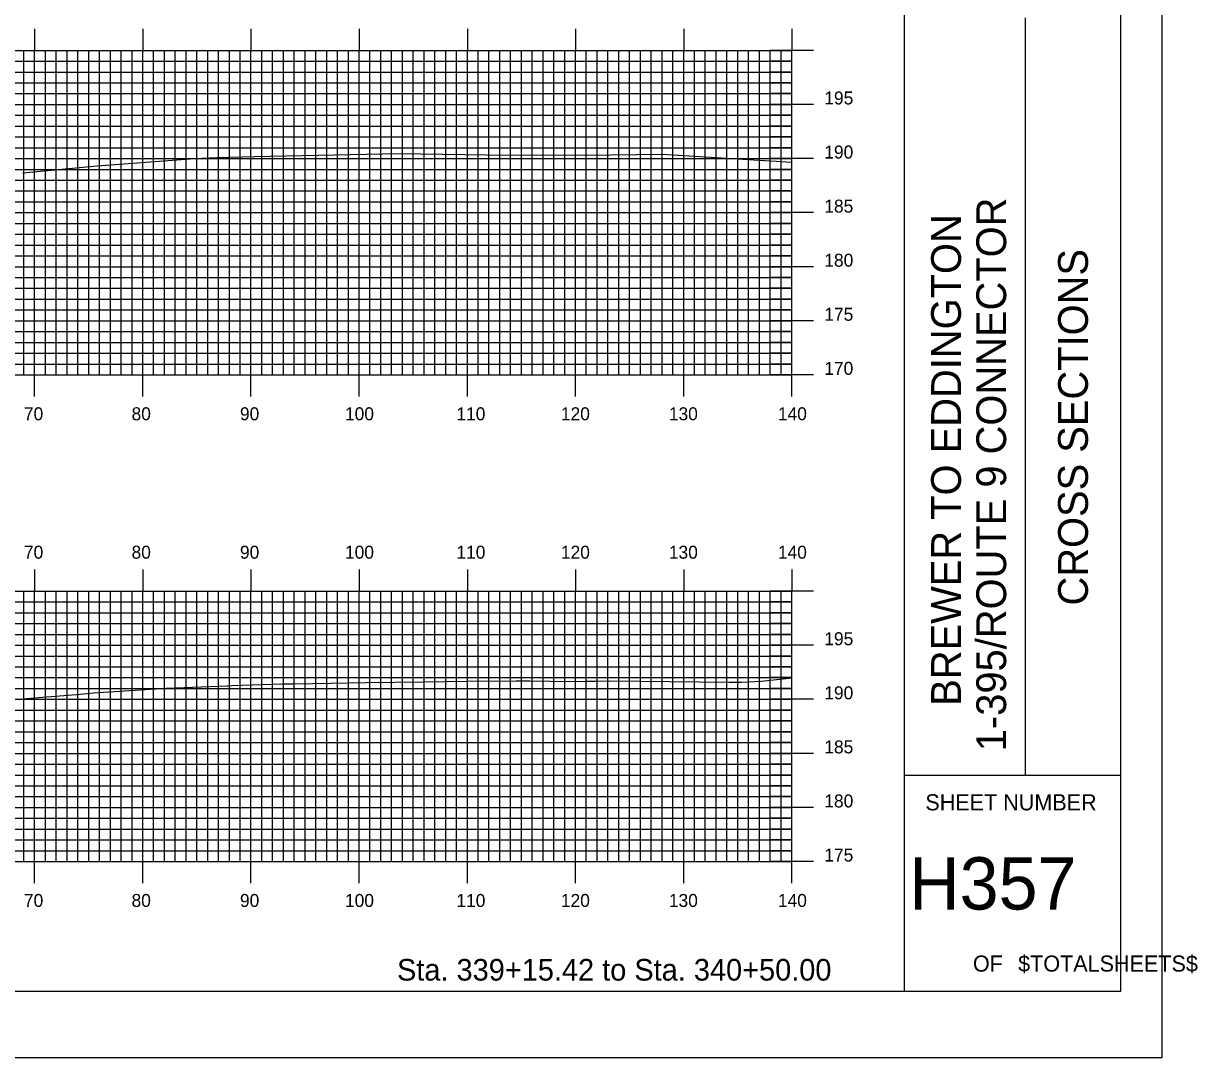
# Model space of a CAD drawing. Extents: x 1824360 to 1824703, y 442591 to 442811.
# Drawn here: x 1824594.3 to 1824702.8, y 442590.5 to 442686.2 of the extents above; entities that cross this region are included whole.
import ezdxf

# ---------------------------------------------------------------- set-up
doc = ezdxf.new("R2010")
doc.units = 0
for name, color, linetype in [('BORDER', 7, 'Continuous'), ('H_V ANNOTATION', 7, 'Continuous'), ('MAJOR', 7, 'Continuous'), ('MINOR', 7, 'Continuous'), ('PLOT BOUNDARY', 7, 'Continuous'), ('S_Roadway_Centerline', 7, 'Continuous')]:
    doc.layers.add(name, color=color, linetype=linetype)

msp = doc.modelspace()

# ---------------------------------------------------------------- linework, layer by layer
at = {"layer": 'BORDER'}
for p, q in [((1824675.73, 442596.67), (1824675.73, 442806.67)), ((1824686.92, 442616.67), (1824686.92, 442686.67)), ((1824675.73, 442616.67), (1824695.73, 442616.67))]:
    msp.add_line(p, q, dxfattribs=at)
msp.add_lwpolyline([(1824375.73, 442596.67), (1824695.73, 442596.67), (1824695.73, 442806.67), (1824375.73, 442806.67)], close=True, dxfattribs=at)
at = {"layer": 'MAJOR'}
for p, q in [((1824595.33, 442685.67), (1824595.33, 442683.67)), ((1824605.33, 442685.67), (1824605.33, 442683.67)), ((1824615.33, 442685.67), (1824615.33, 442683.67)), ((1824625.33, 442685.67), (1824625.33, 442683.67)), ((1824635.33, 442685.67), (1824635.33, 442683.67)), ((1824645.33, 442685.67), (1824645.33, 442683.67)), ((1824655.33, 442685.67), (1824655.33, 442683.67)), ((1824665.33, 442685.67), (1824665.33, 442683.67)), ((1824385.33, 442683.67), (1824665.33, 442683.67)), ((1824385.33, 442683.67), (1824665.33, 442683.67)), ((1824595.33, 442653.67), (1824595.33, 442683.67)), ((1824605.33, 442653.67), (1824605.33, 442683.67)), ((1824615.33, 442653.67), (1824615.33, 442683.67)), ((1824625.33, 442653.67), (1824625.33, 442683.67)), ((1824635.33, 442653.67), (1824635.33, 442683.67)), ((1824645.33, 442653.67), (1824645.33, 442683.67)), ((1824655.33, 442653.67), (1824655.33, 442683.67)), ((1824667.34, 442683.67), (1824663.33, 442683.67)), ((1824665.33, 442653.67), (1824665.33, 442683.67)), ((1824665.33, 442653.67), (1824665.33, 442683.67)), ((1824385.33, 442678.67), (1824665.33, 442678.67)), ((1824667.34, 442678.67), (1824663.33, 442678.67)), ((1824385.33, 442673.67), (1824665.33, 442673.67)), ((1824667.34, 442673.67), (1824663.33, 442673.67)), ((1824385.33, 442668.67), (1824665.33, 442668.67)), ((1824667.34, 442668.67), (1824663.33, 442668.67)), ((1824385.33, 442663.67), (1824665.33, 442663.67)), ((1824667.34, 442663.67), (1824663.33, 442663.67)), ((1824385.33, 442658.67), (1824665.33, 442658.67)), ((1824667.34, 442658.67), (1824663.33, 442658.67)), ((1824385.33, 442653.67), (1824665.33, 442653.67)), ((1824385.33, 442653.67), (1824665.33, 442653.67)), ((1824595.33, 442651.66), (1824595.33, 442653.67)), ((1824605.33, 442651.66), (1824605.33, 442653.67)), ((1824615.33, 442651.66), (1824615.33, 442653.67)), ((1824625.33, 442651.66), (1824625.33, 442653.67)), ((1824635.33, 442651.66), (1824635.33, 442653.67)), ((1824645.33, 442651.66), (1824645.33, 442653.67)), ((1824655.33, 442651.66), (1824655.33, 442653.67)), ((1824667.34, 442653.67), (1824663.33, 442653.67)), ((1824665.33, 442651.66), (1824665.33, 442653.67)), ((1824595.33, 442635.67), (1824595.33, 442633.67)), ((1824605.33, 442635.67), (1824605.33, 442633.67)), ((1824615.33, 442635.67), (1824615.33, 442633.67)), ((1824625.33, 442635.67), (1824625.33, 442633.67)), ((1824635.33, 442635.67), (1824635.33, 442633.67)), ((1824645.33, 442635.67), (1824645.33, 442633.67)), ((1824655.33, 442635.67), (1824655.33, 442633.67)), ((1824665.33, 442635.67), (1824665.33, 442633.67)), ((1824525.33, 442633.67), (1824665.33, 442633.67)), ((1824525.33, 442633.67), (1824665.33, 442633.67)), ((1824595.33, 442608.67), (1824595.33, 442633.67)), ((1824605.33, 442608.67), (1824605.33, 442633.67)), ((1824615.33, 442608.67), (1824615.33, 442633.67)), ((1824625.33, 442608.67), (1824625.33, 442633.67)), ((1824635.33, 442608.67), (1824635.33, 442633.67)), ((1824645.33, 442608.67), (1824645.33, 442633.67)), ((1824655.33, 442608.67), (1824655.33, 442633.67)), ((1824667.34, 442633.67), (1824663.33, 442633.67)), ((1824665.33, 442608.67), (1824665.33, 442633.67)), ((1824665.33, 442608.67), (1824665.33, 442633.67)), ((1824525.33, 442628.67), (1824665.33, 442628.67)), ((1824667.34, 442628.67), (1824663.33, 442628.67)), ((1824525.33, 442623.67), (1824665.33, 442623.67)), ((1824667.34, 442623.67), (1824663.33, 442623.67)), ((1824525.33, 442618.67), (1824665.33, 442618.67)), ((1824667.34, 442618.67), (1824663.33, 442618.67)), ((1824525.33, 442613.67), (1824665.33, 442613.67)), ((1824667.34, 442613.67), (1824663.33, 442613.67)), ((1824525.33, 442608.67), (1824665.33, 442608.67)), ((1824525.33, 442608.67), (1824665.33, 442608.67)), ((1824595.33, 442606.66), (1824595.33, 442608.67)), ((1824605.33, 442606.66), (1824605.33, 442608.67)), ((1824615.33, 442606.66), (1824615.33, 442608.67)), ((1824625.33, 442606.66), (1824625.33, 442608.67)), ((1824635.33, 442606.66), (1824635.33, 442608.67)), ((1824645.33, 442606.66), (1824645.33, 442608.67)), ((1824655.33, 442606.66), (1824655.33, 442608.67)), ((1824667.34, 442608.67), (1824663.33, 442608.67)), ((1824665.33, 442606.66), (1824665.33, 442608.67))]:
    msp.add_line(p, q, dxfattribs=at)
at = {"layer": 'MINOR'}
for p, q in [((1824594.33, 442653.67), (1824594.33, 442683.67)), ((1824596.33, 442653.67), (1824596.33, 442683.67)), ((1824597.33, 442653.67), (1824597.33, 442683.67)), ((1824598.33, 442653.67), (1824598.33, 442683.67)), ((1824599.33, 442653.67), (1824599.33, 442683.67)), ((1824600.33, 442653.67), (1824600.33, 442683.67)), ((1824601.33, 442653.67), (1824601.33, 442683.67)), ((1824602.33, 442653.67), (1824602.33, 442683.67)), ((1824603.33, 442653.67), (1824603.33, 442683.67)), ((1824604.33, 442653.67), (1824604.33, 442683.67)), ((1824606.33, 442653.67), (1824606.33, 442683.67)), ((1824607.33, 442653.67), (1824607.33, 442683.67)), ((1824608.33, 442653.67), (1824608.33, 442683.67)), ((1824609.33, 442653.67), (1824609.33, 442683.67)), ((1824610.33, 442653.67), (1824610.33, 442683.67)), ((1824611.33, 442653.67), (1824611.33, 442683.67)), ((1824612.33, 442653.67), (1824612.33, 442683.67)), ((1824613.33, 442653.67), (1824613.33, 442683.67)), ((1824614.33, 442653.67), (1824614.33, 442683.67)), ((1824616.33, 442653.67), (1824616.33, 442683.67)), ((1824617.33, 442653.67), (1824617.33, 442683.67)), ((1824618.33, 442653.67), (1824618.33, 442683.67)), ((1824619.33, 442653.67), (1824619.33, 442683.67)), ((1824620.33, 442653.67), (1824620.33, 442683.67)), ((1824621.33, 442653.67), (1824621.33, 442683.67)), ((1824622.33, 442653.67), (1824622.33, 442683.67)), ((1824623.33, 442653.67), (1824623.33, 442683.67)), ((1824624.33, 442653.67), (1824624.33, 442683.67)), ((1824626.33, 442653.67), (1824626.33, 442683.67)), ((1824627.33, 442653.67), (1824627.33, 442683.67)), ((1824628.33, 442653.67), (1824628.33, 442683.67)), ((1824629.33, 442653.67), (1824629.33, 442683.67)), ((1824630.33, 442653.67), (1824630.33, 442683.67)), ((1824631.33, 442653.67), (1824631.33, 442683.67)), ((1824632.33, 442653.67), (1824632.33, 442683.67)), ((1824633.33, 442653.67), (1824633.33, 442683.67)), ((1824634.33, 442653.67), (1824634.33, 442683.67)), ((1824636.33, 442653.67), (1824636.33, 442683.67)), ((1824637.33, 442653.67), (1824637.33, 442683.67)), ((1824638.33, 442653.67), (1824638.33, 442683.67)), ((1824639.33, 442653.67), (1824639.33, 442683.67)), ((1824640.33, 442653.67), (1824640.33, 442683.67)), ((1824641.33, 442653.67), (1824641.33, 442683.67)), ((1824642.33, 442653.67), (1824642.33, 442683.67)), ((1824643.33, 442653.67), (1824643.33, 442683.67)), ((1824644.33, 442653.67), (1824644.33, 442683.67)), ((1824646.33, 442653.67), (1824646.33, 442683.67)), ((1824647.33, 442653.67), (1824647.33, 442683.67)), ((1824648.33, 442653.67), (1824648.33, 442683.67)), ((1824649.33, 442653.67), (1824649.33, 442683.67)), ((1824650.33, 442653.67), (1824650.33, 442683.67)), ((1824651.33, 442653.67), (1824651.33, 442683.67)), ((1824652.33, 442653.67), (1824652.33, 442683.67)), ((1824653.33, 442653.67), (1824653.33, 442683.67)), ((1824654.33, 442653.67), (1824654.33, 442683.67)), ((1824656.33, 442653.67), (1824656.33, 442683.67)), ((1824657.33, 442653.67), (1824657.33, 442683.67)), ((1824658.33, 442653.67), (1824658.33, 442683.67)), ((1824659.33, 442653.67), (1824659.33, 442683.67)), ((1824660.33, 442653.67), (1824660.33, 442683.67)), ((1824661.33, 442653.67), (1824661.33, 442683.67)), ((1824662.33, 442653.67), (1824662.33, 442683.67)), ((1824663.33, 442653.67), (1824663.33, 442683.67)), ((1824664.33, 442653.67), (1824664.33, 442683.67)), ((1824385.33, 442682.67), (1824665.33, 442682.67)), ((1824665.33, 442682.67), (1824663.33, 442682.67)), ((1824385.33, 442681.67), (1824665.33, 442681.67)), ((1824665.33, 442681.67), (1824663.33, 442681.67)), ((1824385.33, 442680.67), (1824665.33, 442680.67)), ((1824665.33, 442680.67), (1824663.33, 442680.67)), ((1824385.33, 442679.67), (1824665.33, 442679.67)), ((1824665.33, 442679.67), (1824663.33, 442679.67)), ((1824385.33, 442677.67), (1824665.33, 442677.67)), ((1824665.33, 442677.67), (1824663.33, 442677.67)), ((1824385.33, 442676.67), (1824665.33, 442676.67)), ((1824665.33, 442676.67), (1824663.33, 442676.67)), ((1824385.33, 442675.67), (1824665.33, 442675.67)), ((1824665.33, 442675.67), (1824663.33, 442675.67)), ((1824385.33, 442674.67), (1824665.33, 442674.67)), ((1824665.33, 442674.67), (1824663.33, 442674.67)), ((1824385.33, 442672.67), (1824665.33, 442672.67)), ((1824385.33, 442671.67), (1824665.33, 442671.67)), ((1824665.33, 442672.67), (1824663.33, 442672.67)), ((1824665.33, 442671.67), (1824663.33, 442671.67)), ((1824385.33, 442670.67), (1824665.33, 442670.67)), ((1824665.33, 442670.67), (1824663.33, 442670.67)), ((1824385.33, 442669.67), (1824665.33, 442669.67)), ((1824665.33, 442669.67), (1824663.33, 442669.67)), ((1824385.33, 442667.67), (1824665.33, 442667.67)), ((1824665.33, 442667.67), (1824663.33, 442667.67)), ((1824385.33, 442666.67), (1824665.33, 442666.67)), ((1824665.33, 442666.67), (1824663.33, 442666.67)), ((1824385.33, 442665.67), (1824665.33, 442665.67)), ((1824665.33, 442665.67), (1824663.33, 442665.67)), ((1824385.33, 442664.67), (1824665.33, 442664.67)), ((1824665.33, 442664.67), (1824663.33, 442664.67)), ((1824385.33, 442662.67), (1824665.33, 442662.67)), ((1824665.33, 442662.67), (1824663.33, 442662.67)), ((1824385.33, 442661.67), (1824665.33, 442661.67)), ((1824665.33, 442661.67), (1824663.33, 442661.67)), ((1824385.33, 442660.67), (1824665.33, 442660.67)), ((1824385.33, 442659.67), (1824665.33, 442659.67)), ((1824665.33, 442660.67), (1824663.33, 442660.67)), ((1824665.33, 442659.67), (1824663.33, 442659.67)), ((1824385.33, 442657.67), (1824665.33, 442657.67)), ((1824665.33, 442657.67), (1824663.33, 442657.67)), ((1824385.33, 442656.67), (1824665.33, 442656.67)), ((1824665.33, 442656.67), (1824663.33, 442656.67)), ((1824385.33, 442655.67), (1824665.33, 442655.67)), ((1824665.33, 442655.67), (1824663.33, 442655.67)), ((1824385.33, 442654.67), (1824665.33, 442654.67)), ((1824665.33, 442654.67), (1824663.33, 442654.67)), ((1824594.33, 442608.67), (1824594.33, 442633.67)), ((1824596.33, 442608.67), (1824596.33, 442633.67)), ((1824597.33, 442608.67), (1824597.33, 442633.67)), ((1824598.33, 442608.67), (1824598.33, 442633.67)), ((1824599.33, 442608.67), (1824599.33, 442633.67)), ((1824600.33, 442608.67), (1824600.33, 442633.67)), ((1824601.33, 442608.67), (1824601.33, 442633.67)), ((1824602.33, 442608.67), (1824602.33, 442633.67)), ((1824603.33, 442608.67), (1824603.33, 442633.67)), ((1824604.33, 442608.67), (1824604.33, 442633.67)), ((1824606.33, 442608.67), (1824606.33, 442633.67)), ((1824607.33, 442608.67), (1824607.33, 442633.67)), ((1824608.33, 442608.67), (1824608.33, 442633.67)), ((1824609.33, 442608.67), (1824609.33, 442633.67)), ((1824610.33, 442608.67), (1824610.33, 442633.67)), ((1824611.33, 442608.67), (1824611.33, 442633.67)), ((1824612.33, 442608.67), (1824612.33, 442633.67)), ((1824613.33, 442608.67), (1824613.33, 442633.67)), ((1824614.33, 442608.67), (1824614.33, 442633.67)), ((1824616.33, 442608.67), (1824616.33, 442633.67)), ((1824617.33, 442608.67), (1824617.33, 442633.67)), ((1824618.33, 442608.67), (1824618.33, 442633.67)), ((1824619.33, 442608.67), (1824619.33, 442633.67)), ((1824620.33, 442608.67), (1824620.33, 442633.67)), ((1824621.33, 442608.67), (1824621.33, 442633.67)), ((1824622.33, 442608.67), (1824622.33, 442633.67)), ((1824623.33, 442608.67), (1824623.33, 442633.67)), ((1824624.33, 442608.67), (1824624.33, 442633.67)), ((1824626.33, 442608.67), (1824626.33, 442633.67)), ((1824627.33, 442608.67), (1824627.33, 442633.67)), ((1824628.33, 442608.67), (1824628.33, 442633.67)), ((1824629.33, 442608.67), (1824629.33, 442633.67)), ((1824630.33, 442608.67), (1824630.33, 442633.67)), ((1824631.33, 442608.67), (1824631.33, 442633.67)), ((1824632.33, 442608.67), (1824632.33, 442633.67)), ((1824633.33, 442608.67), (1824633.33, 442633.67)), ((1824634.33, 442608.67), (1824634.33, 442633.67)), ((1824636.33, 442608.67), (1824636.33, 442633.67)), ((1824637.33, 442608.67), (1824637.33, 442633.67)), ((1824638.33, 442608.67), (1824638.33, 442633.67)), ((1824639.33, 442608.67), (1824639.33, 442633.67)), ((1824640.33, 442608.67), (1824640.33, 442633.67)), ((1824641.33, 442608.67), (1824641.33, 442633.67)), ((1824642.33, 442608.67), (1824642.33, 442633.67)), ((1824643.33, 442608.67), (1824643.33, 442633.67)), ((1824644.33, 442608.67), (1824644.33, 442633.67)), ((1824646.33, 442608.67), (1824646.33, 442633.67)), ((1824647.33, 442608.67), (1824647.33, 442633.67)), ((1824648.33, 442608.67), (1824648.33, 442633.67)), ((1824649.33, 442608.67), (1824649.33, 442633.67)), ((1824650.33, 442608.67), (1824650.33, 442633.67)), ((1824651.33, 442608.67), (1824651.33, 442633.67)), ((1824652.33, 442608.67), (1824652.33, 442633.67)), ((1824653.33, 442608.67), (1824653.33, 442633.67)), ((1824654.33, 442608.67), (1824654.33, 442633.67)), ((1824656.33, 442608.67), (1824656.33, 442633.67)), ((1824657.33, 442608.67), (1824657.33, 442633.67)), ((1824658.33, 442608.67), (1824658.33, 442633.67)), ((1824659.33, 442608.67), (1824659.33, 442633.67)), ((1824660.33, 442608.67), (1824660.33, 442633.67)), ((1824661.33, 442608.67), (1824661.33, 442633.67)), ((1824662.33, 442608.67), (1824662.33, 442633.67)), ((1824663.33, 442608.67), (1824663.33, 442633.67)), ((1824664.33, 442608.67), (1824664.33, 442633.67)), ((1824525.33, 442632.67), (1824665.33, 442632.67)), ((1824665.33, 442632.67), (1824663.33, 442632.67)), ((1824525.33, 442631.67), (1824665.33, 442631.67)), ((1824665.33, 442631.67), (1824663.33, 442631.67)), ((1824525.33, 442630.67), (1824665.33, 442630.67)), ((1824665.33, 442630.67), (1824663.33, 442630.67)), ((1824525.33, 442629.67), (1824665.33, 442629.67)), ((1824665.33, 442629.67), (1824663.33, 442629.67)), ((1824525.33, 442627.67), (1824665.33, 442627.67)), ((1824665.33, 442627.67), (1824663.33, 442627.67)), ((1824525.33, 442626.67), (1824665.33, 442626.67)), ((1824665.33, 442626.67), (1824663.33, 442626.67)), ((1824525.33, 442625.67), (1824665.33, 442625.67)), ((1824665.33, 442625.67), (1824663.33, 442625.67)), ((1824525.33, 442624.67), (1824665.33, 442624.67)), ((1824665.33, 442624.67), (1824663.33, 442624.67)), ((1824525.33, 442622.67), (1824665.33, 442622.67)), ((1824665.33, 442622.67), (1824663.33, 442622.67)), ((1824525.33, 442621.67), (1824665.33, 442621.67)), ((1824525.33, 442620.67), (1824665.33, 442620.67)), ((1824665.33, 442621.67), (1824663.33, 442621.67)), ((1824665.33, 442620.67), (1824663.33, 442620.67)), ((1824525.33, 442619.67), (1824665.33, 442619.67)), ((1824665.33, 442619.67), (1824663.33, 442619.67)), ((1824525.33, 442617.67), (1824665.33, 442617.67)), ((1824665.33, 442617.67), (1824663.33, 442617.67)), ((1824525.33, 442616.67), (1824665.33, 442616.67)), ((1824665.33, 442616.67), (1824663.33, 442616.67)), ((1824525.33, 442615.67), (1824665.33, 442615.67)), ((1824665.33, 442615.67), (1824663.33, 442615.67)), ((1824525.33, 442614.67), (1824665.33, 442614.67)), ((1824665.33, 442614.67), (1824663.33, 442614.67)), ((1824525.33, 442612.67), (1824665.33, 442612.67)), ((1824665.33, 442612.67), (1824663.33, 442612.67)), ((1824525.33, 442611.67), (1824665.33, 442611.67)), ((1824665.33, 442611.67), (1824663.33, 442611.67)), ((1824525.33, 442610.67), (1824665.33, 442610.67)), ((1824665.33, 442610.67), (1824663.33, 442610.67)), ((1824525.33, 442609.67), (1824665.33, 442609.67)), ((1824665.33, 442609.67), (1824663.33, 442609.67))]:
    msp.add_line(p, q, dxfattribs=at)
at = {"layer": 'PLOT BOUNDARY'}
msp.add_lwpolyline([(1824359.55, 442590.55), (1824699.55, 442590.55), (1824699.55, 442810.55), (1824359.55, 442810.55)], close=True, dxfattribs=at)
at = {"layer": 'S_Roadway_Centerline'}
for points in [[(1824594.23, 442672.35), (1824601.12, 442672.99), (1824610.1, 442673.67), (1824612.21, 442673.78), (1824615.64, 442673.86), (1824628.97, 442674.14), (1824637.1, 442674.02), (1824646.2, 442673.99), (1824653.33, 442674.08), (1824663.3, 442673.45), (1824663.87, 442673.43), (1824665.33, 442673.34)], [(1824591, 442623.45), (1824595.7, 442623.84), (1824599.2, 442624.11), (1824600.18, 442624.21), (1824600.77, 442624.26), (1824607.5, 442624.69), (1824607.61, 442624.69), (1824609.93, 442624.8), (1824613.1, 442624.93), (1824613.2, 442624.93), (1824613.57, 442624.95), (1824618.25, 442625.09), (1824619.36, 442625.11), (1824626, 442625.22), (1824631.21, 442625.28), (1824635.26, 442625.36), (1824639.83, 442625.37), (1824641.1, 442625.37), (1824644.94, 442625.33), (1824646.33, 442625.34), (1824647.16, 442625.34), (1824648.49, 442625.37), (1824659.52, 442625.26), (1824659.77, 442625.26), (1824659.9, 442625.26), (1824660.11, 442625.25), (1824660.38, 442625.25), (1824660.67, 442625.26), (1824662.45, 442625.35), (1824662.81, 442625.39), (1824665.33, 442625.66)]]:
    msp.add_lwpolyline(points, dxfattribs=at)

# ---------------------------------------------------------------- texts
at = {"layer": 'BORDER'}
for s, p in [('1-395/ROUTE 9 CONNECTOR', (1824685.14, 442618.87)), ('BREWER TO EDDINGTON', (1824680.96, 442623.07)), ('CROSS SECTIONS', (1824692.7, 442632.34))]:
    msp.add_text(s, height=2.7557, rotation=90, dxfattribs=at).set_placement(p)
for s, height, p in [('SHEET NUMBER', 1.4905, (1824677.67, 442613.4)), ('H357', 4.839, (1824676.17, 442604.23)), ('OF', 1.491, (1824682.07, 442598.49)), ('$TOTALSHEETS$', 1.4905, (1824686.25, 442598.49))]:
    msp.add_text(s, height=height, dxfattribs=at).set_placement(p)
at = {"layer": 'H_V ANNOTATION'}
for s, height, p in [('195', 1.2, (1824668.33, 442678.67)), ('190', 1.2, (1824668.33, 442673.67)), ('185', 1.2, (1824668.33, 442668.67)), ('180', 1.2, (1824668.33, 442663.67)), ('175', 1.2, (1824668.33, 442658.67)), ('170', 1.2, (1824668.33, 442653.67)), ('70', 1.2, (1824594.34, 442649.47)), ('80', 1.2, (1824604.29, 442649.47)), ('90', 1.2, (1824614.31, 442649.47)), ('100', 1.2, (1824624.02, 442649.47)), ('110', 1.2, (1824634.32, 442649.47)), ('120', 1.2, (1824643.98, 442649.47)), ('130', 1.2, (1824653.96, 442649.47)), ('140', 1.2, (1824664.04, 442649.47)), ('70', 1.2, (1824594.34, 442636.67)), ('80', 1.2, (1824604.29, 442636.67)), ('90', 1.2, (1824614.31, 442636.67)), ('100', 1.2, (1824624.02, 442636.67)), ('110', 1.2, (1824634.32, 442636.67)), ('120', 1.2, (1824643.98, 442636.67)), ('130', 1.2, (1824653.96, 442636.67)), ('140', 1.2, (1824664.04, 442636.67)), ('195', 1.2, (1824668.33, 442628.67)), ('190', 1.2, (1824668.33, 442623.67)), ('185', 1.2, (1824668.33, 442618.67)), ('180', 1.2, (1824668.33, 442613.67)), ('175', 1.2, (1824668.33, 442608.67)), ('70', 1.2, (1824594.34, 442604.47)), ('80', 1.2, (1824604.29, 442604.47)), ('90', 1.2, (1824614.31, 442604.47)), ('100', 1.2, (1824624.02, 442604.47)), ('110', 1.2, (1824634.32, 442604.47)), ('120', 1.2, (1824643.98, 442604.47)), ('130', 1.2, (1824653.96, 442604.47)), ('140', 1.2, (1824664.04, 442604.47)), ('Sta. 339+15.42 to Sta. 340+50.00', 2.0004, (1824628.83, 442597.66))]:
    msp.add_text(s, height=height, dxfattribs=at).set_placement(p)

doc.saveas('drawing.dxf')
